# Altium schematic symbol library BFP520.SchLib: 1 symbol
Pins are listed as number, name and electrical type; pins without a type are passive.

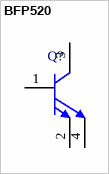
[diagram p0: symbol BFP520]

## BFP520
designator Q?
NPN Silicon RF Transistor, 2.5 V VCEO, 40 mA IC, 23.5 dB Gmax, SOT343, Green; Manufacturer: Infineon; PartNumber: BFP520; Gmax (typ): 23.5 dB; Green: yes; IC (max): 40 mA; NFmin (typ): 0.95 dB; Ptot (max): 100 mW; VCEO (max): 2.5 V
footprint INF-SOT343_V (SOT343, 4-Leads, Body 2x1.25 mm)
pins: 1 B, 2 E, 3 C, 4 E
